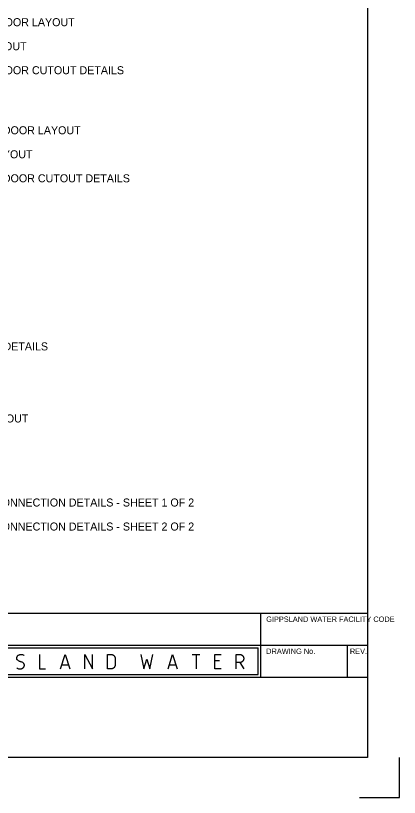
# Model space of a CAD drawing. Extents: x 0 to 841, y 0 to 594.
# Drawn here: x 697 to 841, y 0 to 293 of the extents above; entities that cross this region are included whole.
import ezdxf

# ---------------------------------------------------------------- set-up
doc = ezdxf.new("R2010")
doc.units = 0
doc.layers.add('A1BORDER', color=7, linetype='Continuous')
doc.layers.add('Level 1', color=7, linetype='Continuous')

msp = doc.modelspace()

# ---------------------------------------------------------------- linework, layer by layer
at = {"layer": 'A1BORDER'}
for p, q in [((829, 581), (829, 15)), ((592.5, 69), (829, 69)), ((789, 45), (789, 69)), ((28, 57), (829, 57)), ((637, 56), (788, 56)), ((788, 46), (788, 56)), ((821.5, 45), (821.5, 57)), ((663, 46), (788, 46)), ((664, 45), (829, 45)), ((829, 15), (28, 15)), ((829, 15), (829, 15)), ((841, 0), (841, 15)), ((826, 0), (841, 0))]:
    msp.add_line(p, q, dxfattribs=at)
for points in [[(697.45, 48.46), (697.67, 48.36), (697.9, 48.27), (698.12, 48.21), (698.36, 48.17), (698.6, 48.16), (698.84, 48.16), (698.87, 48.16), (699.03, 48.18), (699.18, 48.21), (699.33, 48.26), (699.48, 48.32), (699.62, 48.4), (699.72, 48.46), (699.81, 48.53), (699.9, 48.61), (699.98, 48.69), (700.05, 48.78), (700.11, 48.88), (700.17, 48.99), (700.22, 49.09), (700.25, 49.21), (700.28, 49.32), (700.29, 49.36), (700.3, 49.44), (700.3, 49.52), (700.3, 49.61), (700.29, 49.69), (700.27, 49.77), (700.25, 49.86), (700.22, 49.93), (700.18, 50.01), (700.14, 50.09), (700.09, 50.15), (700.04, 50.21), (700.01, 50.25), (699.85, 50.39), (699.69, 50.51), (699.52, 50.61), (699.34, 50.7), (699.15, 50.78), (698.95, 50.83), (698.87, 50.85), (698.68, 50.9), (698.49, 50.96), (698.3, 51.04), (698.12, 51.14), (697.96, 51.26), (697.8, 51.39), (697.73, 51.45), (697.67, 51.51), (697.62, 51.57), (697.58, 51.64), (697.53, 51.71), (697.5, 51.79), (697.47, 51.87), (697.46, 51.95), (697.44, 52.04), (697.43, 52.12), (697.43, 52.21), (697.44, 52.29), (697.45, 52.35), (697.47, 52.46), (697.51, 52.58), (697.55, 52.69), (697.61, 52.79), (697.67, 52.89), (697.74, 52.99), (697.82, 53.07), (697.9, 53.15), (697.99, 53.23), (698.02, 53.24), (698.15, 53.33), (698.3, 53.4), (698.44, 53.45), (698.6, 53.5), (698.75, 53.52), (698.87, 53.54), (699.11, 53.55), (699.35, 53.53), (699.58, 53.49), (699.82, 53.43), (700.04, 53.35), (700.27, 53.25)], [(705.96, 53.54), (705.96, 48.16), (708.23, 48.16)], [(713.91, 48.16), (715.61, 53.54), (717.32, 48.16)], [(722.99, 48.16), (722.99, 53.54), (725.83, 48.16), (725.83, 53.54)], [(731.52, 48.16), (731.52, 53.54), (732.94, 53.54), (733.06, 53.54), (733.18, 53.52), (733.3, 53.49), (733.42, 53.45), (733.53, 53.4), (733.64, 53.34), (733.75, 53.27), (733.84, 53.19), (733.94, 53.1), (734.02, 53), (734.09, 52.9), (734.16, 52.79), (734.22, 52.67), (734.27, 52.56), (734.31, 52.43), (734.33, 52.31), (734.35, 52.18), (734.36, 52.05), (734.36, 49.66), (734.35, 49.52), (734.33, 49.39), (734.31, 49.27), (734.27, 49.14), (734.22, 49.02), (734.16, 48.91), (734.09, 48.8), (734.02, 48.7), (733.94, 48.6), (733.84, 48.51), (733.75, 48.43), (733.64, 48.36), (733.53, 48.3), (733.42, 48.25), (733.3, 48.21), (733.18, 48.18), (733.06, 48.16), (732.94, 48.16), (731.52, 48.16)], [(744.01, 53.54), (745.14, 48.16), (746.28, 51.75), (747.41, 48.16), (748.55, 53.54)], [(754.22, 48.16), (755.92, 53.54), (757.63, 48.16)], [(763.31, 53.54), (766.15, 53.54)], [(764.73, 53.54), (764.73, 48.16)], [(774.09, 48.16), (771.82, 48.16), (771.82, 53.54), (774.09, 53.54)], [(779.78, 48.16), (779.78, 53.54), (781.2, 53.54), (781.32, 53.54), (781.44, 53.52), (781.56, 53.49), (781.68, 53.45), (781.79, 53.4), (781.9, 53.34), (782.01, 53.27), (782.1, 53.19), (782.2, 53.1), (782.28, 53), (782.35, 52.9), (782.42, 52.79), (782.48, 52.67), (782.53, 52.56), (782.56, 52.43), (782.59, 52.31), (782.61, 52.18), (782.61, 52.05), (782.61, 51.91), (782.59, 51.78), (782.56, 51.66), (782.53, 51.53), (782.48, 51.42), (782.42, 51.3), (782.35, 51.19), (782.28, 51.09), (782.2, 50.99), (782.1, 50.9), (782.01, 50.82), (781.9, 50.75), (781.79, 50.69), (781.68, 50.64), (781.56, 50.6), (781.44, 50.57), (781.32, 50.55), (781.2, 50.55), (779.78, 50.55)], [(773.53, 51.15), (771.82, 51.15)], [(781.2, 50.55), (782.61, 48.16)], [(714.48, 49.66), (716.75, 49.66)], [(754.79, 49.66), (757.06, 49.66)]]:
    msp.add_lwpolyline(points, dxfattribs=at)

# ---------------------------------------------------------------- texts
for s, height, p in [('GIPPSLAND WATER FACILITY CODE', 1.99998, (791.03, 65.77)), ('DRAWING No.', 1.99998, (791.03, 53.77)), ('REV.', 2, (822.43, 53.77))]:
    msp.add_text(s, height=height, dxfattribs=at).set_placement(p)
at = {"layer": 'Level 1'}
for s, p in [('PUMP STATION 30kW TO 45kW (VSD) - CT METERED - VSD CUBICLE - CONTROL COMPARTMENT - ESCUTCHEON DOOR LAYOUT', (470, 288.999)), ('PUMP STATION 30kW TO 45kW (VSD) - CT METERED - VSD CUBICLE - CONTROL COMPARTMENT - GEAR TRAY LAYOUT', (470, 280)), ('PUMP STATION 30kW TO 45kW (VSD) - CT METERED - VSD CUBICLE - CONTROL COMPARTMENT - ESCUTCHEON DOOR CUTOUT DETAILS', (470, 271)), ('PUMP STATION 55kW TO 160kW (VSD) - CT METERED - VSD CUBICLE - CONTROL COMPARTMENT - ESCUTCHEON DOOR LAYOUT', (470, 248.499)), ('PUMP STATION 55kW TO 160kW (VSD) - CT METERED - VSD CUBICLE - CONTROL COMPARTMENT - GEAR TRAY LAYOUT', (470, 239.5)), ('PUMP STATION 55kW TO 160kW (VSD) - CT METERED - VSD CUBICLE - CONTROL COMPARTMENT - ESCUTCHEON DOOR CUTOUT DETAILS', (470, 230.5)), ('PUMP STATION 55kW TO 160kW (VSD) - JUNCTION BOX QB1EJ01 - SECTIONAL ARRANGEMENTS & ROOF CANOPY DETAILS', (470, 167.5)), ('PUMP STATION 55kW TO 160kW (VSD) - JUNCTION BOX QB1EJ01 - INSTRUMENT COMPARTMENT - GEAR TRAY LAYOUT', (470, 140.5)), ('PUMP STATION 30kW TO 160kW (VSD) - CT METERED - ELECTRICAL CUBICLE SHELTER - MEMBER LAYOUT AND CONNECTION DETAILS - SHEET 1 OF 2', (470, 109)), ('PUMP STATION 30kW TO 160kW (VSD) - CT METERED - ELECTRICAL CUBICLE SHELTER - MEMBER LAYOUT AND CONNECTION DETAILS - SHEET 2 OF 2', (470, 100))]:
    msp.add_text(s, height=3, dxfattribs=at).set_placement(p)

doc.saveas('drawing.dxf')
